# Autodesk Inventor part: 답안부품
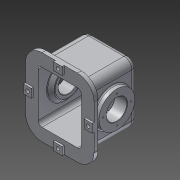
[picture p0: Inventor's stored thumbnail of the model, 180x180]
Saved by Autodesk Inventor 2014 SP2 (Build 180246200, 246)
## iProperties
Created: 2014-11
Part Number: 답안부품
Material: 알루미늄 6061
Document SubType Name: Modeling
Designer: 201-07
Density: 2.71 g/cm^3
Appearance: 알루미늄 - 평지
Mass: 2881.88 g
Surface Area: 2078.9 cm^2
Volume: 1063.42 cm^3
Author: 201-07
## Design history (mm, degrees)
sketch "스케치1"
  geometry: L1 (87, 98)-(-87, 98); L2 (-87, 98)-(-87, -98); L3 (-87, -98)-(87, -98); L4 (87, -98)-(87, 98); L5 (87, 98)-(-87, -98); L6 (-87, 98)-(87, -98); 1 further point
  constraints: 12 end point, 2 midpoint, 2 parallel, 1 horizontal, 1 perpendicular
  dimensions: "d0" = 174 distance of L3.end L2.end; "d1" = 196 distance of L2.end L1.end
extrude "돌출1" new body sketch "스케치1" distance "d2" = 10; taper "d3" = 0 deg
sketch "스케치2"
  geometry: L1 (-65, 76)-(65, 76); L2 (65, 76)-(65, -76); L3 (65, -76)-(-65, -76); L4 (-65, -76)-(-65, 76); L5 (-65, 76)-(65, -76); L6 (65, 76)-(-65, -76); 1 further point
  constraints: 12 end point, 2 midpoint, 2 parallel, 1 horizontal, 1 perpendicular
  dimensions: "d4" = 130 distance of L2.end L3.end; "d5" = 152 distance of L1.end L2.end
extrude "돌출2" new body sketch "스케치2" distance "d6" = 118; taper "d7" = 0 deg
sketch "스케치3"
  geometry: L1 (-87, 98)-(87, 98) reference; L2 (-87, -98)-(-87, 98) reference; L3 (87, -98)-(-87, -98) reference; L4 (-87, 11)-(-67, 11); L5 (-67, 11)-(-67, -11); L6 (-67, -11)-(-87, -11); L7 (-87, -11)-(-87, 11); L8 (0, 98)-(0, -98); L9 (87, 11)-(67, 11); L10 (67, 11)-(67, -11); L11 (67, -11)-(87, -11); L12 (87, -11)-(87, 11); L13 (-87, 0)-(87, 0); L14 (-11, 98)-(11, 98); L15 (11, 98)-(11, 78); L16 (11, 78)-(-11, 78); L17 (-11, 78)-(-11, 98); L18 (11, -98)-(11, -78); L19 (11, -78)-(-11, -78); L20 (-11, -98)-(11, -98); L21 (-11, -78)-(-11, -98); 6 further points
  constraints: 36 end point, 10 symmetric about line, 7 midpoint, 4 parallel, 2 horizontal, 2 perpendicular, 1 collinear, 1 horizontal alignment, 1 point on line, 1 vertical alignment
  dimensions: "d8" = 20 distance of L4.start L4.end; "d9" = 22 distance of L4.end L5.end; "d10" = 22 distance of L15.end L16.end; "d11" = 20 distance of L14.end L15.end
extrude "돌출3" join sketch "스케치3" distance "d12" = 5; taper "d13" = 0 deg
sketch "스케치4"
  geometry: L1 (87, -15)-(65, -15) reference; L2 (87, -10)-(174, -10) reference; C1 r 45.5 at (76, 58); 2 further points
  constraints: 1 centre point, 1 midpoint, 1 vertical alignment
  dimensions: "d14" = 91 diameter of C1; "d83" = 68 distance from line of L2 C1.centre
extrude "돌출4" join sketch "스케치4" distance "d16" = 12; taper "d17" = 0 deg
fillet "모깎기1" dims "d18" = 42
fillet "모깎기2" dims "d19" = 20
fillet "모깎기3" dims "d20" = 10
feature "쉘1" dims "d21" = 10
sketch "스케치6"
  geometry: L1 (-45, 66)-(45, 66) reference; L2 (55, 56)-(55, -56) reference; L3 (45, -66)-(-45, -66) reference; L4 (-55, -56)-(-55, 56) reference; L5 (65, -56)-(65, 56) reference; L6 (45, 76)-(-45, 76) reference; L7 (-65, 56)-(-65, -56) reference; L8 (-45, -76)-(45, -76) reference; A1 r 10 centre (-45, 56) between (-45, 66) and (-55, 56) reference; A2 r 10 centre (45, 56) between (55, 56) and (45, 66) reference; A3 r 10 centre (45, -56) between (45, -66) and (55, -56) reference; A4 r 10 centre (-45, -56) between (-55, -56) and (-45, -66) reference; A5 r 20 centre (45, -56) between (45, -76) and (65, -56) reference; A6 r 20 centre (45, 56) between (65, 56) and (45, 76) reference; A7 r 20 centre (-45, 56) between (-45, 76) and (-65, 56) reference; A8 r 20 centre (-45, -56) between (-65, -56) and (-45, -76) reference
extrude "돌출5" cut sketch "스케치6" stored distance "d22" = 12; taper "d23" = 0 deg
sketch "스케치7"
  geometry: C1 r 45.5 at (56, 58) reference; 1 further point
  node "투영된 루프2"
node "작업 평면1"
sketch "스케치9"
  geometry: C1 r 35.5 at (56, 58); C2 r 45.5 at (56, 58) reference; 1 further point
  constraints: 1 centre point, 1 concentric
  dimensions: "d25" = 71 diameter of C1
feature "로프트1" sketch "스케치9" dims "d26" = 0, "d27" = 90 deg, "d28" = 0, "d29" = 90 deg
feature "결합1"
  node "솔리드2"
sketch "스케치10"
  geometry: C1 r 45.5 at (0, 0) reference; C2 r 26 at (0, 0); 1 further point
  constraints: 1 centre point, 1 coincident
  dimensions: "d30" = 52 diameter of C2
extrude "돌출6" cut sketch "스케치10" distance "d31" = 32; taper "d32" = 0 deg
sketch "스케치12"
  geometry: L1 (68, 0)-(152.121, -17.88); L2 (152.121, -17.88)-(158.566, 12.442); L3 (158.566, 12.442)-(124.445, 19.695); L4 (118, -10.628)-(124.445, 19.695); L5 (118, -56)-(118, 56) reference; L6 (68, -1.176)-(68, -26); 1 further point
  constraints: 10 end point, 3 perpendicular, 2 point on line, 1 parallel, 1 vertical alignment, 1 other
  dimensions: "d39" = 86 distance of L1.start L1.end; "d42" = 62 diameter of L2.end L1; "d43" = 78 deg angle of L6 L1
revolve "회전1" sketch "스케치12" stored, may be unused: angle "d44" = 90 deg
sketch "스케치13"
  geometry: L1 (-10, 10)-(-10, 122) reference; L2 (90, 0)-(0, 0); L3 (100, 122)-(100, 10) reference; L4 (0, 132)-(90, 132) reference; L5 (14, 55.372)-(76, 55.372) reference; L6 (-10, 10)-(-10, 122) reference; L7 (90, 0)-(0, 0) reference; L8 (100, 122)-(100, 10) reference; L9 (0, 132)-(90, 132) reference; A1 r 10 centre (0, 122) between (0, 132) and (-10, 122) reference; A2 r 10 centre (0, 10) between (-10, 10) and (0, 0) reference; A3 r 10 centre (90, 10) between (90, 0) and (100, 10) reference; A4 r 10 centre (90, 122) between (100, 122) and (90, 132) reference; A5 r 10 centre (0, 122) between (0, 132) and (-10, 122) reference; A6 r 10 centre (0, 10) between (-10, 10) and (0, 0) reference; A7 r 10 centre (90, 10) between (90, 0) and (100, 10) reference; A8 r 10 centre (90, 122) between (100, 122) and (90, 132) reference; 1 further point; 1 other entity
  constraints: 2 end point, 1 other
extrude "돌출7" cut sketch "스케치13" distance "d45" = 10; taper "d46" = 0 deg
sketch "스케치14"
  geometry: C1 r 31 at (0, 0) reference; 2 further points
  constraints: 1 coincident
hole "구멍1" sketch "스케치14" at (0, 0) diameter "d47" = 30; stored, may be unused: countersink angle "d51" = 90 deg, drill point angle "d53" = 118 deg; dims "d48" = 6, "d49" = 42, "d50" = 25, "d52" = 8
sketch "스케치15"
  geometry: L1 (-65, -56)-(-65, 56) reference; L2 (-45, 76)-(45, 76) reference; L3 (65, 56)-(65, -56) reference; L4 (45, -76)-(-45, -76) reference; L5 (-87, 56)-(-87, -56) reference; L6 (-45, -98)-(45, -98) reference; L7 (87, -56)-(87, 56) reference; L8 (45, 98)-(-45, 98) reference; L9 (-77, 0)-(77, 0); L10 (0, 88)-(0, -88); L11 (87, -56)-(87, 56) reference; A1 r 20 centre (-45, 56) between (-45, 76) and (-65, 56) reference; A2 r 20 centre (45, 56) between (65, 56) and (45, 76) reference; A3 r 20 centre (45, -56) between (45, -76) and (65, -56) reference; A4 r 20 centre (-45, -56) between (-65, -56) and (-45, -76) reference; A5 r 42 centre (-45, 56) between (-45, 98) and (-87, 56) reference; A6 r 42 centre (-45, -56) between (-87, -56) and (-45, -98) reference; A7 r 42 centre (45, -56) between (45, -98) and (87, -56) reference; A8 r 42 centre (45, 56) between (87, 56) and (45, 98) reference; 3 further points
  constraints: 4 coincident, 4 end point, 2 midpoint, 2 parallel, 1 perpendicular
  dimensions: "d77" = 176 distance of L10.end L10.start; "d78" = 10 distance from line of L11 L9.end
hole "구멍2" sketch "스케치15" at (77, 0), (-77, 0), (0, 88), (0, -88) diameter "d58" = 9; stored, may be unused: countersink angle "d62" = 90 deg, drill point angle "d64" = 118 deg; dims "d59" = 6, "d60" = 14, "d61" = 8.6, "d63" = 8
sketch "스케치16" dims "d65" = 70
  geometry: C1 r 26 at (0, 0) reference; C2 r 45.5 at (0, 0) reference; 6 further points
  constraints: 2 vertical alignment, 1 coincident, 7 other
  dimensions: "d68" = 360 deg dimension on C1.centre point (0, 35) (derived)
hole "구멍3" sketch "스케치16" at (0, 35), (-35, 0), (0, -35), (35, 0) diameter "d70" = 3.242; stored, may be unused: countersink angle "d74" = 90 deg, drill point angle "d76" = 118 deg; dims "d71" = 13, "d72" = 14, "d73" = 8.6, "d75" = 16
chamfer "모따기1" distance "d79" = 1; stored, may be unused: second distance "d80" = 2, angle "d81" = 45 deg
fillet "모깎기4" dims "d82" = 0.3
fillet "모깎기5" dims "d84" = 3
sketch "스케치17"
  geometry: L1 (56, -118)-(90, -118) reference; L2 (56, -123)-(34, -123) reference; 2 further points
  constraints: 1 midpoint, 1 vertical alignment, 1 other
  dimensions: "d85" = 92 distance from line of L1 point (45, -26)
feature "엠보싱1" sketch "스케치17" dims "d0" = 174, "d1" = 196, "d86" = 1, "d87" = 0
fillet "모깎기6" dims "d88" = 3
node "솔리드1"
mirror "대칭2"
mirror "대칭3"
node "투영된 루프1"
node "투영된 루프3"
node "투영된 루프4"
node "투영된 루프5"
